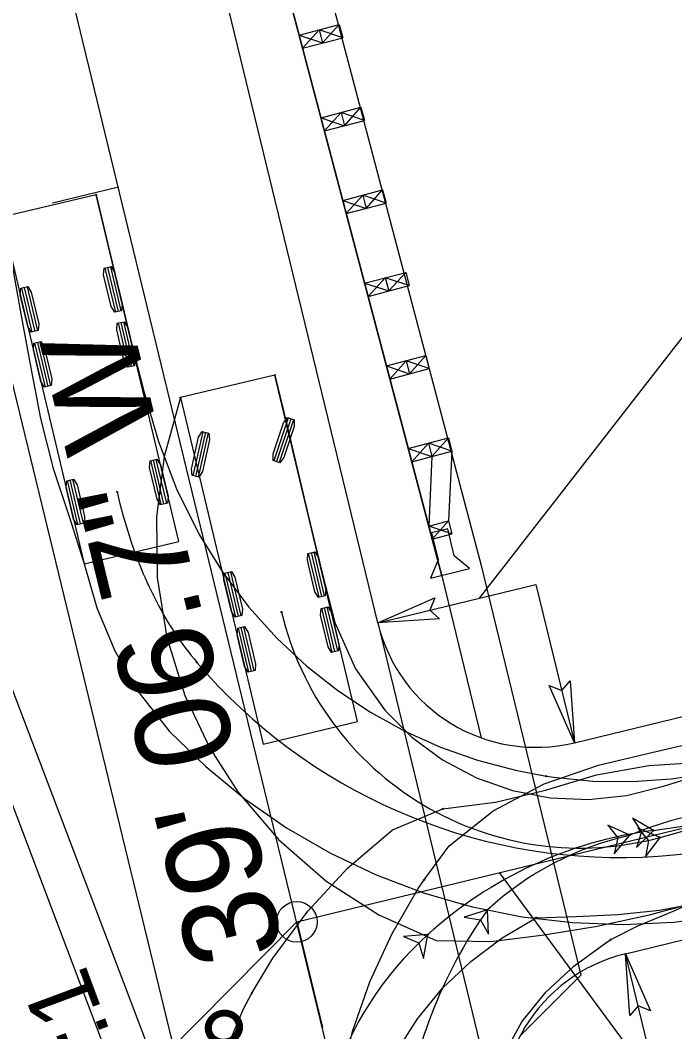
# Model space of a CAD drawing. Extents: x 1735795 to 1737428, y 699740 to 701024.
# Drawn here: x 1736230.5 to 1736278.8, y 700327 to 700401.5 of the extents above; entities that cross this region are included whole.
import ezdxf

# ---------------------------------------------------------------- set-up
doc = ezdxf.new("R2010")
doc.units = 0
for name, color, linetype in [('Prop Dimension', 7, 'Continuous'), ('Prop Dimension Text', 7, 'Continuous'), ('Prop EOT', 7, 'Continuous'), ('Prop Guardrail Anchor Unit CELL', 7, 'Continuous'), ('Prop Horizontal Alignment', 7, 'Continuous'), ('Prop Horizontal Alignment Direction Label', 7, 'Continuous'), ('Prop Horizontal Alignment Station Label', 7, 'Continuous'), ('Prop Horizontal Alignment Tick Large', 7, 'Continuous'), ('Prop Horizontal Alignment Tick Small', 7, 'Continuous'), ('Prop Paved Shoulder', 7, 'Continuous'), ('Prop Terminator CELL', 7, 'Continuous'), ('Scratch_Level_1', 7, 'Continuous'), ('Scratch_Level_2', 7, 'Continuous'), ('Scratch_Level_4', 7, 'Continuous'), ('Scratch_Level_5', 7, 'Continuous'), ('Scratch_Level_6', 7, 'Continuous'), ('Scratch_Level_7', 7, 'Continuous')]:
    doc.layers.add(name, color=color, linetype=linetype)

msp = doc.modelspace()

# ---------------------------------------------------------------- linework, layer by layer
at = {"layer": 'Prop Dimension'}
for points in [[(1736264.391, 700358.911), (1736306.256, 700412.699), (1736300.944, 700434.969)], [(1736256.888, 700357.089), (1736268.549, 700359.921), (1736271.381, 700348.26)], [(1736266.329, 700318.219), (1736277.99, 700321.051), (1736275.157, 700332.712)]]:
    msp.add_lwpolyline(points, dxfattribs=at)
at = {"layer": 'Prop EOT'}
for p, q in [((1736256.888, 700357.089), (1736211.496, 700543.975)), ((1736261.304, 700245.692), (1736190.118, 700538.782)), ((1736256.888, 700357.089), (1736266.329, 700318.219)), ((1736271.381, 700348.26), (1736281.795, 700350.789)), ((1736275.157, 700332.712), (1736285.572, 700335.241))]:
    msp.add_line(p, q, dxfattribs=at)
for centre, start, end in [((1736268.549, 700359.921), 193.65186, 283.65186), ((1736277.99, 700321.051), 103.65186, 193.65186)]:
    msp.add_arc(centre, 12, start, end, dxfattribs=at)
at = {"layer": 'Prop Guardrail Anchor Unit CELL'}
for p, q in [((1736248.839, 700408.943), (1736260.779, 700363.742)), ((1736251.097, 700400.393), (1736254.049, 700401.172)), ((1736252.829, 700399.815), (1736254.049, 700401.172)), ((1736254.049, 700401.172), (1736254.304, 700400.205)), ((1736251.097, 700400.393), (1736252.829, 700399.815)), ((1736252.573, 700400.782), (1736251.353, 700399.425)), ((1736252.573, 700400.782), (1736252.829, 700399.815)), ((1736254.304, 700400.205), (1736252.573, 700400.782)), ((1736251.353, 700399.425), (1736254.304, 700400.205)), ((1736252.707, 700394.3), (1736255.653, 700395.079)), ((1736254.181, 700394.689), (1736252.962, 700393.333)), ((1736254.181, 700394.689), (1736254.436, 700393.722)), ((1736255.909, 700394.112), (1736254.181, 700394.689)), ((1736254.436, 700393.722), (1736255.653, 700395.079)), ((1736255.653, 700395.079), (1736255.909, 700394.112)), ((1736252.707, 700394.3), (1736254.436, 700393.722)), ((1736252.962, 700393.333), (1736255.909, 700394.112)), ((1736254.316, 700388.208), (1736257.251, 700388.984)), ((1736255.784, 700388.595), (1736254.572, 700387.241)), ((1736255.784, 700388.595), (1736256.04, 700387.628)), ((1736257.506, 700388.017), (1736255.784, 700388.595)), ((1736256.04, 700387.628), (1736257.251, 700388.984)), ((1736257.251, 700388.984), (1736257.506, 700388.017)), ((1736254.316, 700388.208), (1736254.572, 700387.241)), ((1736254.316, 700388.208), (1736256.04, 700387.628)), ((1736254.572, 700387.241), (1736257.506, 700388.017)), ((1736255.925, 700382.116), (1736258.959, 700382.917)), ((1736257.442, 700382.517), (1736256.181, 700381.149)), ((1736257.442, 700382.517), (1736257.697, 700381.55)), ((1736259.214, 700381.95), (1736257.442, 700382.517)), ((1736257.697, 700381.55), (1736258.959, 700382.917)), ((1736258.959, 700382.917), (1736259.214, 700381.95)), ((1736255.925, 700382.116), (1736257.697, 700381.55)), ((1736256.181, 700381.149), (1736259.214, 700381.95)), ((1736257.535, 700376.023), (1736260.435, 700376.79)), ((1736259.241, 700375.44), (1736260.435, 700376.79)), ((1736260.435, 700376.79), (1736260.69, 700375.823)), ((1736257.535, 700376.023), (1736259.241, 700375.44)), ((1736258.985, 700376.407), (1736257.79, 700375.056)), ((1736257.79, 700375.056), (1736260.69, 700375.823)), ((1736258.985, 700376.407), (1736259.241, 700375.44)), ((1736260.69, 700375.823), (1736258.985, 700376.407)), ((1736259.144, 700369.931), (1736262.106, 700370.713)), ((1736260.881, 700369.355), (1736262.106, 700370.713)), ((1736262.106, 700370.713), (1736262.362, 700369.746)), ((1736259.144, 700369.931), (1736260.881, 700369.355)), ((1736260.626, 700370.322), (1736259.4, 700368.964)), ((1736260.626, 700370.322), (1736260.881, 700369.355)), ((1736262.362, 700369.746), (1736260.626, 700370.322)), ((1736259.4, 700368.964), (1736262.362, 700369.746)), ((1736260.881, 700369.355), (1736260.651, 700364.226)), ((1736262.362, 700369.746), (1736262.102, 700364.609)), ((1736260.651, 700364.226), (1736262.102, 700364.609)), ((1736262.357, 700363.642), (1736260.651, 700364.226)), ((1736261.454, 700363.876), (1736260.86, 700363.73)), ((1736260.907, 700363.259), (1736262.102, 700364.609)), ((1736262.047, 700364.022), (1736261.454, 700363.876)), ((1736262.534, 700362.034), (1736262.047, 700364.022)), ((1736262.102, 700364.609), (1736262.23, 700364.125)), ((1736262.102, 700364.609), (1736262.357, 700363.642)), ((1736260.86, 700363.73), (1736261.347, 700361.742)), ((1736260.907, 700363.259), (1736262.357, 700363.642)), ((1736261.347, 700361.742), (1736260.79, 700360.395)), ((1736263.646, 700361.093), (1736262.534, 700362.034)), ((1736260.79, 700360.395), (1736263.646, 700361.093))]:
    msp.add_line(p, q, dxfattribs=at)
at = {"layer": 'Prop Horizontal Alignment'}
for p, q in [((1736284.975, 700194.842), (1736200.807, 700541.379)), ((1736250.919, 700335.057), (1736283.684, 700343.015))]:
    msp.add_line(p, q, dxfattribs=at)
at = {"layer": 'Prop Horizontal Alignment Station Label'}
for p, q in [((1736288.213, 700308.426), (1736265.869, 700338.689)), ((1736250.919, 700335.057), (1736104.013, 700186.731))]:
    msp.add_line(p, q, dxfattribs=at)
msp.add_circle((1736250.919, 700335.057), 1.5, dxfattribs=at)
at = {"layer": 'Prop Horizontal Alignment Tick Large'}
msp.add_line((1736250.919, 700335.057), (1736252.807, 700327.283), dxfattribs=at)
at = {"layer": 'Prop Horizontal Alignment Tick Small'}
msp.add_line((1736237.771, 700389.192), (1736232.912, 700388.012), dxfattribs=at)
at = {"layer": 'Prop Paved Shoulder'}
for p, q in [((1736261.611, 700360.555), (1736248.829, 700408.94)), ((1736261.611, 700360.555), (1736264.509, 700348.621)), ((1736245.174, 700312.106), (1736229.723, 700352.809))]:
    msp.add_line(p, q, dxfattribs=at)
at = {"layer": 'Prop Terminator CELL'}
for points in [[(1736261.443, 700357.398), (1736256.888, 700357.089), (1736261.096, 700358.934), (1736260.726, 700358.021)], [(1736271.072, 700352.816), (1736271.381, 700348.26), (1736269.536, 700352.468), (1736270.449, 700352.098)], [(1736275.466, 700328.156), (1736275.157, 700332.712), (1736277.003, 700328.504), (1736276.09, 700328.874)]]:
    msp.add_lwpolyline(points, close=True, dxfattribs=at)
at = {"layer": 'Scratch_Level_1'}
msp.add_lwpolyline([(1736241.472, 700439.271), (1736248.839, 700408.943), (1736261.621, 700360.557)], dxfattribs=at)
at = {"layer": 'Scratch_Level_2'}
for p, q in [((1736264.521, 700361.323), (1736271.854, 700331.131)), ((1736242.334, 700311.086), (1736226.832, 700351.945)), ((1736267.37, 700326.64), (1736271.854, 700331.131))]:
    msp.add_line(p, q, dxfattribs=at)
msp.add_lwpolyline([(1736244.388, 700439.979), (1736251.747, 700409.68), (1736264.521, 700361.323)], dxfattribs=at)
at = {"layer": 'Scratch_Level_4'}
for p, q in [((1736236.132, 700388.628), (1736229.175, 700386.97)), ((1736242.217, 700363.097), (1736236.132, 700388.628)), ((1736229.175, 700386.97), (1736235.26, 700361.438)), ((1736236.979, 700383.275), (1736237.752, 700380.033)), ((1736237.182, 700383.324), (1736237.955, 700380.081)), ((1736236.777, 700383.227), (1736237.55, 700379.985)), ((1736230.63, 700381.762), (1736231.403, 700378.519)), ((1736230.833, 700381.81), (1736231.606, 700378.568)), ((1736231.035, 700381.859), (1736231.808, 700378.616)), ((1736237.743, 700379.174), (1736238.516, 700375.931)), ((1736237.945, 700379.222), (1736238.718, 700375.98)), ((1736238.148, 700379.27), (1736238.921, 700376.028)), ((1736231.596, 700377.709), (1736232.369, 700374.466)), ((1736231.799, 700377.757), (1736232.572, 700374.515)), ((1736232.001, 700377.805), (1736232.774, 700374.563)), ((1736241.133, 700365.847), (1736240.361, 700369.089)), ((1736241.336, 700365.895), (1736240.563, 700369.138)), ((1736240.931, 700365.799), (1736240.158, 700369.041)), ((1736234.987, 700364.382), (1736234.214, 700367.624)), ((1736235.189, 700364.43), (1736234.416, 700367.673)), ((1736234.784, 700364.334), (1736234.011, 700367.576)), ((1736235.26, 700361.438), (1736242.217, 700363.097)), ((1736242.217, 700363.097), (1736242.217, 700363.097))]:
    msp.add_line(p, q, dxfattribs=at)
for points in [[(1736236.132, 700388.628), (1736237.001, 700384.981), (1736237.871, 700381.334), (1736238.742, 700377.687), (1736239.667, 700374.053), (1736240.738, 700370.461), (1736242.06, 700366.954), (1736243.719, 700363.597), (1736243.719, 700363.597), (1736245.46, 700360.799), (1736247.396, 700358.239), (1736249.481, 700355.936), (1736251.669, 700353.9), (1736253.946, 700352.108), (1736256.357, 700350.511), (1736258.888, 700349.116), (1736261.523, 700347.932), (1736264.245, 700346.967), (1736267.035, 700346.226), (1736269.304, 700345.799)], [(1736229.175, 700386.97), (1736229.964, 700383.303), (1736230.635, 700379.601), (1736231.325, 700375.888), (1736232.037, 700372.146), (1736232.963, 700368.458), (1736234.154, 700364.934), (1736235.26, 700361.438), (1736235.26, 700361.438), (1736235.26, 700361.438), (1736236.193, 700358.206), (1736237.519, 700355.025), (1736239.288, 700351.959), (1736241.537, 700349.096), (1736244.209, 700346.497), (1736247.094, 700344.128), (1736250.164, 700342), (1736253.399, 700340.13), (1736256.775, 700338.528), (1736260.272, 700337.207), (1736263.14, 700336.357)], [(1736269.304, 700345.799), (1736269.875, 700345.716), (1736272.747, 700345.438), (1736275.632, 700345.395), (1736278.51, 700345.586), (1736281.363, 700346.012), (1736284.171, 700346.668), (1736286.917, 700347.55), (1736289.582, 700348.653), (1736292.148, 700349.97), (1736294.598, 700351.49), (1736296.917, 700353.204), (1736299.113, 700355.074), (1736301.213, 700357.052), (1736303.248, 700359.099), (1736305.249, 700361.179), (1736307.234, 700363.277), (1736309.218, 700365.406), (1736311.264, 700367.635)], [(1736237.674, 700366.736), (1736237.751, 700366.411), (1736237.831, 700366.088), (1736237.913, 700365.765), (1736237.997, 700365.442), (1736238.085, 700365.12), (1736238.174, 700364.799), (1736238.267, 700364.479), (1736238.362, 700364.16), (1736238.46, 700363.841), (1736238.561, 700363.524), (1736238.665, 700363.207), (1736238.772, 700362.891), (1736238.881, 700362.576), (1736238.994, 700362.263), (1736239.11, 700361.95), (1736239.229, 700361.639), (1736239.351, 700361.329), (1736239.477, 700361.02), (1736239.606, 700360.712), (1736239.738, 700360.406), (1736239.873, 700360.102), (1736240.012, 700359.799), (1736240.155, 700359.497), (1736240.301, 700359.198), (1736240.45, 700358.9), (1736240.603, 700358.604), (1736240.76, 700358.309), (1736240.92, 700358.017), (1736241.084, 700357.727), (1736241.252, 700357.439), (1736241.423, 700357.153), (1736241.598, 700356.869), (1736241.777, 700356.588), (1736241.96, 700356.309), (1736242.146, 700356.033), (1736242.337, 700355.759), (1736242.531, 700355.488), (1736242.729, 700355.22), (1736242.931, 700354.955), (1736243.137, 700354.693), (1736243.346, 700354.434), (1736243.56, 700354.178)], [(1736263.14, 700336.357), (1736263.865, 700336.174), (1736267.53, 700335.438), (1736271.244, 700335.002), (1736274.981, 700334.87), (1736278.717, 700335.043), (1736282.426, 700335.519), (1736286.085, 700336.296), (1736289.668, 700337.368), (1736293.152, 700338.729), (1736296.513, 700340.368), (1736299.73, 700342.276), (1736302.782, 700344.439), (1736305.647, 700346.843), (1736308.306, 700349.473), (1736310.743, 700352.311)]]:
    msp.add_lwpolyline(points, dxfattribs=at)
for points in [[(1736236.726, 700383.215), (1736237.232, 700383.336), (1736237.493, 700382.918), (1736238.049, 700380.583), (1736238.005, 700380.093), (1736237.499, 700379.973), (1736237.239, 700380.39), (1736236.682, 700382.725)], [(1736230.58, 700381.75), (1736231.086, 700381.871), (1736231.346, 700381.453), (1736231.903, 700379.118), (1736231.858, 700378.628), (1736231.353, 700378.508), (1736231.092, 700378.925), (1736230.536, 700381.26)], [(1736237.693, 700379.162), (1736238.198, 700379.282), (1736238.459, 700378.865), (1736239.015, 700376.53), (1736238.971, 700376.04), (1736238.465, 700375.919), (1736238.205, 700376.337), (1736237.648, 700378.672)], [(1736231.546, 700377.697), (1736232.052, 700377.817), (1736232.312, 700377.4), (1736232.869, 700375.065), (1736232.824, 700374.575), (1736232.319, 700374.454), (1736232.058, 700374.872), (1736231.502, 700377.207)], [(1736241.386, 700365.907), (1736240.88, 700365.787), (1736240.62, 700366.204), (1736240.063, 700368.539), (1736240.108, 700369.029), (1736240.613, 700369.15), (1736240.874, 700368.732), (1736241.43, 700366.397)], [(1736235.24, 700364.442), (1736234.734, 700364.322), (1736234.473, 700364.739), (1736233.917, 700367.074), (1736233.961, 700367.564), (1736234.467, 700367.685), (1736234.727, 700367.267), (1736235.284, 700364.932)]]:
    msp.add_lwpolyline(points, close=True, dxfattribs=at)
for centre in [(1736236.132, 700388.628), (1736237.674, 700366.736), (1736243.56, 700354.178), (1736243.56, 700354.178), (1736269.304, 700345.799), (1736269.304, 700345.799), (1736263.14, 700336.357), (1736263.14, 700336.357)]:
    msp.add_circle(centre, 0.0417, dxfattribs=at)
msp.add_arc((1736274.725, 700380.778), 40.974, 220.48156, 324.13897, dxfattribs=at)
at = {"layer": 'Scratch_Level_5'}
for p, q in [((1736249.309, 700375.344), (1736242.352, 700373.686)), ((1736255.394, 700349.813), (1736249.309, 700375.344)), ((1736242.352, 700373.686), (1736248.437, 700348.154)), ((1736242.352, 700373.686), (1736242.352, 700373.686)), ((1736250.296, 700372.194), (1736249.225, 700369.038)), ((1736250.493, 700372.127), (1736249.423, 700368.971)), ((1736250.691, 700372.06), (1736249.62, 700368.904)), ((1736243.988, 700371.175), (1736243.248, 700367.925)), ((1736244.191, 700371.129), (1736243.451, 700367.878)), ((1736244.394, 700371.082), (1736243.654, 700367.832)), ((1736252.568, 700358.977), (1736251.795, 700362.22)), ((1736252.77, 700359.025), (1736251.997, 700362.268)), ((1736252.973, 700359.074), (1736252.2, 700362.316)), ((1736246.421, 700357.512), (1736245.648, 700360.755)), ((1736246.623, 700357.56), (1736245.851, 700360.803)), ((1736246.826, 700357.609), (1736246.053, 700360.851)), ((1736253.534, 700354.924), (1736252.761, 700358.167)), ((1736253.736, 700354.972), (1736252.963, 700358.215)), ((1736253.939, 700355.021), (1736253.166, 700358.263)), ((1736247.387, 700353.459), (1736246.614, 700356.701)), ((1736247.59, 700353.507), (1736246.817, 700356.75)), ((1736247.792, 700353.556), (1736247.019, 700356.798)), ((1736248.437, 700348.154), (1736255.394, 700349.813))]:
    msp.add_line(p, q, dxfattribs=at)
for points in [[(1736249.309, 700375.344), (1736249.309, 700375.344), (1736250.178, 700371.697), (1736251.048, 700368.049), (1736251.917, 700364.402), (1736252.786, 700360.755), (1736253.725, 700357.127), (1736255.246, 700353.712), (1736257.4, 700350.663), (1736257.4, 700350.663), (1736259.399, 700348.672), (1736261.67, 700346.998), (1736264.164, 700345.678), (1736266.825, 700344.74), (1736269.595, 700344.205), (1736272.414, 700344.085), (1736275.219, 700344.382), (1736277.959, 700345.062), (1736280.661, 700345.893), (1736283.332, 700346.825), (1736286.035, 700347.885), (1736288.667, 700349.034)], [(1736242.352, 700373.686), (1736241.146, 700369.359), (1736240.571, 700364.909), (1736240.637, 700360.428), (1736241.343, 700356.006), (1736242.669, 700351.74), (1736244.504, 700347.857), (1736246.566, 700344.647), (1736246.566, 700344.647), (1736249.571, 700341.123), (1736253.065, 700338.081), (1736256.969, 700335.588), (1736261.198, 700333.698), (1736265.23, 700333.62), (1736269.155, 700334.092), (1736273.07, 700334.751), (1736277.013, 700335.608), (1736280.992, 700336.676), (1736284.974, 700337.958), (1736288.782, 700339.393), (1736291.733, 700340.652)]]:
    msp.add_lwpolyline(points, dxfattribs=at)
for points in [[(1736250.247, 700372.211), (1736250.74, 700372.044), (1736250.738, 700371.552), (1736249.967, 700369.279), (1736249.669, 700368.887), (1736249.176, 700369.054), (1736249.178, 700369.547), (1736249.949, 700371.819)], [(1736243.937, 700371.186), (1736244.444, 700371.071), (1736244.493, 700370.581), (1736243.961, 700368.241), (1736243.705, 700367.821), (1736243.198, 700367.936), (1736243.149, 700368.426), (1736243.681, 700370.766)], [(1736253.023, 700359.086), (1736252.517, 700358.965), (1736252.257, 700359.383), (1736251.7, 700361.717), (1736251.744, 700362.208), (1736252.25, 700362.328), (1736252.511, 700361.911), (1736253.067, 700359.576)], [(1736246.876, 700357.621), (1736246.371, 700357.5), (1736246.11, 700357.918), (1736245.554, 700360.252), (1736245.598, 700360.743), (1736246.104, 700360.863), (1736246.364, 700360.446), (1736246.921, 700358.111)], [(1736253.989, 700355.033), (1736253.483, 700354.912), (1736253.223, 700355.33), (1736252.666, 700357.664), (1736252.71, 700358.155), (1736253.216, 700358.275), (1736253.477, 700357.857), (1736254.033, 700355.523)], [(1736247.842, 700353.568), (1736247.337, 700353.447), (1736247.076, 700353.865), (1736246.52, 700356.199), (1736246.564, 700356.69), (1736247.07, 700356.81), (1736247.33, 700356.392), (1736247.887, 700354.058)], [(1736277.704, 700341.28), (1736276.051, 700341.961), (1736276.841, 700341.047), (1736276.618, 700339.859)]]:
    msp.add_lwpolyline(points, close=True, dxfattribs=at)
for centre in [(1736249.309, 700375.344), (1736242.352, 700373.686), (1736249.793, 700357.888), (1736277.704, 700341.28), (1736277.704, 700341.28)]:
    msp.add_circle(centre, 0.0417, dxfattribs=at)
for centre, radius, start, end in [((1736257.104, 700417.702), 79.15, 285.0858, 314.35399), ((1736271.813, 700363.136), 22.636, 193.40592, 285.0858)]:
    msp.add_arc(centre, radius, start, end, dxfattribs=at)
at = {"layer": 'Scratch_Level_6'}
for points in [[(1736260.309, 700338.167), (1736262.15, 700340.669), (1736265.405, 700343.241), (1736269.16, 700345.218), (1736273.17, 700346.615), (1736277.199, 700347.571), (1736281, 700348.448), (1736284.874, 700348.91), (1736286.825, 700348.985)], [(1736274.075, 700333.748), (1736276.071, 700334.764), (1736278.319, 700335.703), (1736280.473, 700336.623), (1736282.617, 700337.563), (1736284.843, 700338.567), (1736287.304, 700339.629), (1736289.778, 700340.666), (1736291.015, 700341.184)], [(1736260.697, 700297.789), (1736259.1, 700301.289), (1736257.784, 700304.922), (1736256.847, 700308.666), (1736256.368, 700312.38), (1736256.007, 700315.941), (1736255.069, 700319.571), (1736254.131, 700323.201), (1736254.131, 700323.201), (1736255.038, 700326.972), (1736256.307, 700330.638), (1736257.926, 700334.165), (1736259.88, 700337.519), (1736260.309, 700338.167)], [(1736267.622, 700299.579), (1736266.684, 700303.209), (1736265.746, 700306.839), (1736264.892, 700310.489), (1736264.472, 700314.209), (1736264.53, 700317.951), (1736265.067, 700321.652), (1736266.161, 700325.22), (1736266.161, 700325.22), (1736266.161, 700325.22), (1736267.509, 700327.691), (1736269.275, 700329.877), (1736271.338, 700331.784), (1736273.601, 700333.447), (1736274.075, 700333.748)]]:
    msp.add_lwpolyline(points, dxfattribs=at)
for points in [[(1736275.464, 700341.441), (1736273.841, 700342.191), (1736274.592, 700341.244), (1736274.319, 700340.067)], [(1736264.977, 700335.94), (1736263.268, 700335.415), (1736264.459, 700335.212), (1736265.043, 700334.154)]]:
    msp.add_lwpolyline(points, close=True, dxfattribs=at)
for centre in [(1736275.464, 700341.441), (1736275.464, 700341.441), (1736260.309, 700338.167), (1736260.309, 700338.167), (1736264.977, 700335.94), (1736264.977, 700335.94), (1736274.075, 700333.748), (1736274.075, 700333.748)]:
    msp.add_circle(centre, 0.0417, dxfattribs=at)
for centre, radius, start, end in [((1736287.209, 700312.736), 31.015, 88.77924, 112.25367), ((1736280.491, 700319.11), 22.889, 102.68732, 132.66923), ((1736293.447, 700315.706), 34.928, 144.5971, 173.51766)]:
    msp.add_arc(centre, radius, start, end, dxfattribs=at)
at = {"layer": 'Scratch_Level_7'}
for points in [[(1736261.689, 700343.387), (1736265.563, 700343.891), (1736269.266, 700344.774), (1736273.016, 700345.882), (1736276.864, 700346.571), (1736280.765, 700346.832), (1736284.609, 700346.958), (1736287.791, 700347.963), (1736290.733, 700349.088), (1736293.612, 700350.368), (1736296.427, 700351.781), (1736299.173, 700353.326), (1736301.858, 700355.007), (1736304.46, 700356.813), (1736306.974, 700358.741), (1736309.394, 700360.785)], [(1736268.555, 700335.366), (1736271.506, 700335.45), (1736274.583, 700335.611), (1736277.666, 700335.921), (1736280.686, 700336.479), (1736283.654, 700337.168), (1736286.547, 700337.962), (1736289.827, 700339.014), (1736293.254, 700340.291), (1736296.618, 700341.734), (1736299.915, 700343.339), (1736303.135, 700345.104), (1736306.204, 700346.982), (1736309.181, 700349.002), (1736312.059, 700351.161), (1736314.831, 700353.454)], [(1736247.603, 700329.802), (1736249.159, 700332.385), (1736251.725, 700335.847), (1736254.672, 700339.007), (1736257.975, 700341.83), (1736261.689, 700343.387)], [(1736258.746, 700326.215), (1736259.832, 700327.922), (1736261.653, 700330.167), (1736263.756, 700332.151), (1736266.069, 700333.886), (1736268.555, 700335.366)], [(1736253.169, 700292.713), (1736253.169, 700292.713), (1736250.371, 700296.086), (1736248.042, 700299.795), (1736246.222, 700303.773), (1736244.94, 700307.952), (1736244.218, 700312.254), (1736244.061, 700316.472), (1736244.38, 700320.277), (1736244.38, 700320.277), (1736245.312, 700324.675), (1736247, 700328.66), (1736247.603, 700329.802)]]:
    msp.add_lwpolyline(points, dxfattribs=at)
for points in [[(1736277.221, 700341.801), (1736275.674, 700342.698), (1736276.335, 700341.686), (1736275.955, 700340.539)], [(1736260.572, 700334.119), (1736258.79, 700333.974), (1736259.909, 700333.519), (1736260.25, 700332.36)]]:
    msp.add_lwpolyline(points, close=True, dxfattribs=at)
for centre in [(1736261.689, 700343.387), (1736261.689, 700343.387), (1736277.221, 700341.801), (1736277.221, 700341.801), (1736268.555, 700335.366), (1736268.555, 700335.366), (1736260.572, 700334.119), (1736260.572, 700334.119), (1736247.603, 700329.802), (1736247.603, 700329.802)]:
    msp.add_circle(centre, 0.0417, dxfattribs=at)
for centre, radius, start, end in [((1736269.686, 700399.742), 58.429, 277.40991, 292.87649), ((1736281.184, 700311.33), 30.728, 97.40991, 132.12967), ((1736277.324, 700315.598), 24.973, 132.12967, 192.5438)]:
    msp.add_arc(centre, radius, start, end, dxfattribs=at)

# ---------------------------------------------------------------- texts
at = {"layer": 'Prop Dimension Text'}
msp.add_text('8:1', height=5, rotation=110.41421, dxfattribs=at).set_placement((1736238.53, 700323.299))
at = {"layer": 'Prop Horizontal Alignment Direction Label'}
msp.add_text('N 13%%d 39\' 06.7" W', height=7, rotation=103.65186, dxfattribs=at).set_placement((1736256.186, 700307.582))

doc.saveas('drawing.dxf')
